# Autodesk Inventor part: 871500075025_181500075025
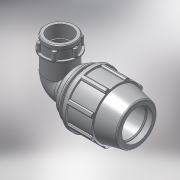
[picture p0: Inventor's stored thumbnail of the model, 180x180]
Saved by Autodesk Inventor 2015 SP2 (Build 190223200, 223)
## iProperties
Created: 2017-02
Part Number: 871500075025_181500075025
Material: PVC-Piping
Description: PLASSON 90° ELBOW FEMALE ADAPTOR 75-2.1/2"
Document SubType Name: Modeling
Designer: KIM
Mass: 92.6774 g
Surface Area: 199.44 cm^2
Volume: 66.1981 cm^3
Density: 1.4 g/cm^3
Appearance: Smooth - White
Author: KIM
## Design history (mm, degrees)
derived "87150.ipt"
feature "Solid1::87150.ipt"
tag "TaggingFeature1"
body "Solid1"
other parameters: "d2" = 75, "d4" = 16.33333, "d5" = 49, "d7" = 132, "d9" = 28, "d11" = 6.53333, "d13" = 120 deg, "d14" = 97.5, "d15" = 12 deg, "d16" = 114.84, "d18" = 3.75, "d19" = 35 deg, "d20" = 17.5 deg, "d21" = 122.76, "d23" = 0, "d25" = 360 deg, "d27" = 2.64, "d33" = 1.5, "d42" = 72.52, "d43" = 3.96, "d46" = 2.25, "d51" = 196, "d68" = 13.06667, "d72" = 105, "d73" = 93.8938, "d74" = 36, "d75" = 107.97787, "d76" = 72.226, "d77" = 39.6, "d79" = 28.8904, "d80" = 2.16678, "d83" = 0, "d84" = 0, "d91" = 99, "d93" = 137, "d94" = 72.226, "d95" = 50.5582, "d96" = 13.06667, "d97" = 50 deg, "d98" = 65.0034, "d99" = 0.5, "d100" = 0.5, "d101" = 12, "d102" = 93.8938, "d103" = 30.96, "d104" = 0, "d108" = 360 deg, "d110" = 2.81681, "d111" = 8.8, "d112" = 0, "d113" = 3.26667, "d114" = 3.26667, "d115" = 111.3948, "d_" = 75, "E_" = 132, "A_" = 196, "l_" = 137, "l_2" = 36, "A_1" = 105, "Rp_" = 72.226, "d105" = 14.08407
